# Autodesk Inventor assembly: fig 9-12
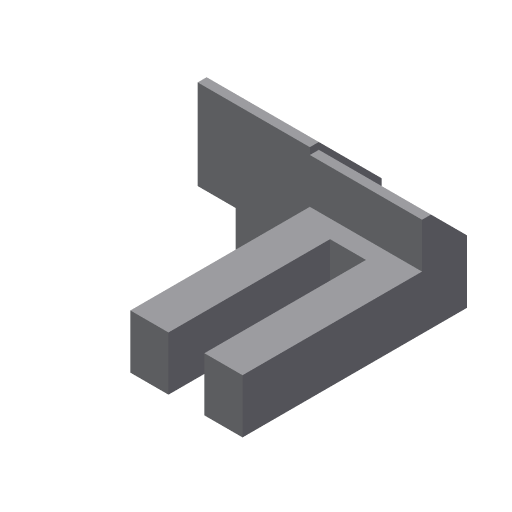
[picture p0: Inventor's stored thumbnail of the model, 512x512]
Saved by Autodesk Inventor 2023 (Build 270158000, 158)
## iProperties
Created: 2002-01
Part Number: fig 9-12
Document SubType Name: Assembly
Designer: ***
Control State: 0
Master: False
Checked Out: False
Shininess: 64.0
Length Units: 11269
Angle Units: 11279
Time Units: 11290
Mass Units: 11283
Length Display Precision: 3
Angle Display Precision: 2
Density: 0.0
Volumn: 0.0
Area: 0.0
PropertySet Name: Model Information
Author: ***
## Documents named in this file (3)
- D:\PROJECTS\Project 2022\Autodesk Inventor For Professional 2023\RESOURCES INVENTOR 2023\RESOURCES INVENTOR 2023\Inventor_2023_Part\Inventor_2023_Part\c09_Inv_2023_prt\fig 9-12.iam
- D:\PROJECTS\Project 2022\Autodesk Inventor For Professional 2023\RESOURCES INVENTOR 2023\RESOURCES INVENTOR 2023\Inventor_2023_Part\Inventor_2023_Part\c09_Inv_2023_prt\Part3.ipt
- D:\PROJECTS\Project 2022\Autodesk Inventor For Professional 2023\RESOURCES INVENTOR 2023\RESOURCES INVENTOR 2023\Inventor_2023_Part\Inventor_2023_Part\c09_Inv_2023_prt\Part4.ipt
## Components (2 placed, 2 different names)
1. Part3:1 — Flush:1, Flush:2, Flush:3, Mate:1
2. Part4:1 — Flush:1, Flush:2, Flush:3, Mate:1
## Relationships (4: Flush 3, Mate 1)
- Flush:1: Part3:1 ↔ Part4:1
- Flush:2: Part3:1 ↔ Part4:1
- Flush:3: Part3:1 ↔ Part4:1
- Mate:1: Part3:1 ↔ Part4:1
